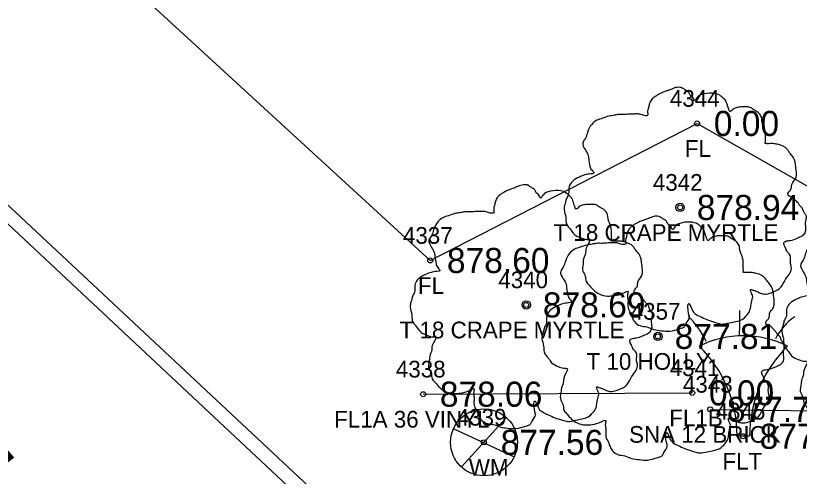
# Model space of a CAD drawing. Extents: x 1622501 to 1626664, y 1117816 to 1121579.
# Drawn here: x 1625412.78 to 1625459.66, y 1120695.23 to 1120722.81 of the extents above; entities that cross this region are included whole.
import ezdxf

# ---------------------------------------------------------------- set-up
doc = ezdxf.new("R2010")
doc.units = 0
for name, color, linetype in [('RD_EX_BldgApp', 7, 'Continuous'), ('RD_EX_BldgApp_txCode', 7, 'Continuous'), ('RD_EX_Conc', 7, 'Continuous'), ('RD_EX_Fence_Other', 7, 'Continuous'), ('RD_EX_Fence_Other_txCode', 7, 'Continuous'), ('RD_EX_Road', 7, 'Continuous'), ('RD_EX_TX_BldgApp_ELEV', 7, 'Continuous'), ('RD_EX_TX_Fence_Other_ELEV', 7, 'Continuous'), ('RD_EX_TX_UT_ELEV', 7, 'Continuous'), ('RD_EX_TX_VEG_ELEV', 7, 'Continuous'), ('RD_EX_UT', 7, 'Continuous'), ('RD_EX_UT_txCode', 7, 'Continuous'), ('RD_EX_VEG', 7, 'Continuous'), ('RD_EX_VEG_txCode', 7, 'Continuous'), ('RD_HC_Data', 7, 'Continuous'), ('RD_SMD_Locator', 7, 'Continuous')]:
    doc.layers.add(name, color=color, linetype=linetype)

msp = doc.modelspace()

# ---------------------------------------------------------------- linework, layer by layer
at = {"layer": 'RD_EX_BldgApp'}
for p, q in [((1625454.325, 1120699.245), (1625464.474, 1120699.109)), ((1625455.937, 1120697.651), (1625456.687, 1120697.651))]:
    msp.add_line(p, q, dxfattribs=at)
for centre, radius, start, end in [((1625449.619, 1120701.293), 4.895, 24.3279, 46.2665), ((1625418.23, 1120704.989), 37.876, 358.0671, 0.2715), ((1625461.2, 1120702.044), 3.283, 123.2906, 154.4886), ((1625456.312, 1120697.651), 5.997, 63.7794, 116.2206), ((1625448.437, 1120697.651), 7.5, 0, 45.8366), ((1625464.187, 1120697.651), 7.5, 134.1634, 180)]:
    msp.add_arc(centre, radius, start, end, dxfattribs=at)
at = {"layer": 'RD_EX_Conc'}
msp.add_lwpolyline([(1625371.324, 1120758.09), (1625374.405, 1120748.878), (1625381, 1120740.913), (1625403.527, 1120719.673), (1625432.461, 1120692.614), (1625438.681, 1120687.207)], dxfattribs=at)
at = {"layer": 'RD_EX_Fence_Other'}
msp.add_line((1625437.153, 1120700.153), (1625453.252, 1120700.233), dxfattribs=at)
msp.add_lwpolyline([(1625435.579, 1120742.173), (1625418.734, 1120725.47), (1625437.576, 1120708.158), (1625453.545, 1120716.361), (1625468.822, 1120707.682)], dxfattribs=at)
at = {"layer": 'RD_EX_Road'}
msp.add_lwpolyline([(1625370.364, 1120757.883), (1625373.672, 1120748.564), (1625380.435, 1120740.201), (1625402.846, 1120719.199), (1625431.886, 1120691.989), (1625438.078, 1120686.6), (1625445.87, 1120680.321), (1625455.5, 1120677.046), (1625462.434, 1120676.301), (1625468.216, 1120676.722), (1625470.162, 1120677.112), (1625477.587, 1120679.763), (1625479.605, 1120680.725), (1625482.392, 1120682.638), (1625486.867, 1120686.354)], dxfattribs=at)
at = {"layer": 'RD_EX_UT'}
for p, q in [((1625439.44, 1120695.812), (1625442.108, 1120698.709)), ((1625438.959, 1120698.108), (1625442.59, 1120696.395))]:
    msp.add_line(p, q, dxfattribs=at)
msp.add_circle((1625440.792, 1120697.27), 2, dxfattribs=at)
at = {"layer": 'RD_EX_VEG'}
for centre, radius in [((1625452.527, 1120711.331), 0.25), ((1625452.514, 1120711.312), 0.0001), ((1625443.319, 1120705.497), 0.25), ((1625443.306, 1120705.478), 0.0001), ((1625451.203, 1120703.613), 0.25), ((1625451.19, 1120703.594), 0.0001)]:
    msp.add_circle(centre, radius, dxfattribs=at)
for points in [[(1625452.659, 1120718.498), (1625452.359, 1120718.523), (1625452.034, 1120718.423), (1625451.784, 1120718.323), (1625451.559, 1120718.248), (1625451.334, 1120718.148), (1625451.035, 1120717.974), (1625450.81, 1120717.774), (1625450.685, 1120717.524), (1625450.635, 1120717.299), (1625450.585, 1120717.024), (1625450.585, 1120716.849), (1625450.46, 1120716.824), (1625450.31, 1120716.849), (1625450.06, 1120716.924), (1625449.81, 1120716.924), (1625449.56, 1120716.924), (1625449.21, 1120716.899), (1625448.86, 1120716.899), (1625448.586, 1120716.849), (1625448.261, 1120716.799), (1625447.886, 1120716.674), (1625447.536, 1120716.549), (1625447.236, 1120716.299), (1625446.986, 1120715.824), (1625446.861, 1120715.475), (1625446.711, 1120715.225), (1625446.861, 1120714.775), (1625447.036, 1120714.425), (1625447.061, 1120714.225), (1625447.136, 1120713.8), (1625447.236, 1120713.575), (1625447.361, 1120713.375), (1625447.286, 1120713.351), (1625446.911, 1120713.301), (1625446.611, 1120713.201), (1625446.187, 1120712.976), (1625445.962, 1120712.751), (1625445.862, 1120712.426), (1625445.837, 1120712.076), (1625445.737, 1120711.876), (1625445.662, 1120711.601), (1625445.637, 1120711.526), (1625445.587, 1120711.201), (1625445.687, 1120710.752), (1625445.712, 1120710.402), (1625445.837, 1120710.177), (1625445.987, 1120710.002), (1625446.162, 1120709.752), (1625446.561, 1120709.527), (1625446.886, 1120709.427), (1625447.086, 1120709.402), (1625446.911, 1120708.902), (1625446.861, 1120708.553), (1625446.736, 1120708.153), (1625446.736, 1120708.078), (1625446.686, 1120707.603), (1625446.836, 1120707.278), (1625446.911, 1120706.903), (1625447.086, 1120706.678), (1625447.361, 1120706.379), (1625447.686, 1120706.154), (1625448.186, 1120706.029), (1625448.586, 1120706.054), (1625449.16, 1120706.229), (1625449.41, 1120706.304), (1625449.385, 1120706.129), (1625449.41, 1120705.754), (1625449.41, 1120705.329), (1625449.56, 1120705.004), (1625449.66, 1120704.729), (1625449.81, 1120704.479), (1625450.135, 1120704.255), (1625450.535, 1120704.18), (1625450.96, 1120704.03), (1625451.409, 1120703.955), (1625451.909, 1120703.93), (1625452.509, 1120704.08), (1625452.784, 1120704.205), (1625452.884, 1120704.379), (1625453.084, 1120704.754), (1625453.034, 1120704.979), (1625453.059, 1120705.579), (1625453.159, 1120705.404), (1625453.334, 1120705.054), (1625453.833, 1120704.754), (1625454.233, 1120704.579), (1625454.708, 1120704.429), (1625455.008, 1120704.354), (1625455.483, 1120704.429), (1625455.857, 1120704.504), (1625456.232, 1120704.629), (1625456.532, 1120704.904), (1625456.707, 1120705.179), (1625456.757, 1120705.454), (1625456.832, 1120705.829), (1625456.882, 1120706.004)], [(1625456.882, 1120706.004), (1625456.807, 1120706.179), (1625456.757, 1120706.429), (1625456.832, 1120706.404), (1625457.007, 1120706.354), (1625457.282, 1120706.229), (1625457.507, 1120706.154), (1625457.832, 1120706.179), (1625458.106, 1120706.279), (1625458.556, 1120706.554), (1625458.831, 1120707.028), (1625459.106, 1120707.428), (1625459.181, 1120707.753), (1625459.131, 1120707.978), (1625459.106, 1120708.478), (1625458.906, 1120708.728), (1625458.856, 1120708.852), (1625458.756, 1120709.252), (1625458.831, 1120709.302), (1625459.106, 1120709.352), (1625459.481, 1120709.477), (1625459.756, 1120709.602), (1625459.981, 1120709.777), (1625460.056, 1120710.002), (1625460.031, 1120710.402), (1625460.081, 1120710.802), (1625460.006, 1120710.952), (1625459.906, 1120711.101), (1625459.831, 1120711.301), (1625459.681, 1120711.451), (1625459.581, 1120711.601), (1625459.481, 1120711.701), (1625459.356, 1120711.851), (1625459.181, 1120711.976), (1625459.031, 1120712.026), (1625458.981, 1120712.176), (1625459.131, 1120712.376), (1625459.181, 1120712.476), (1625459.206, 1120712.701), (1625459.431, 1120713.051), (1625459.481, 1120713.45), (1625459.431, 1120713.875), (1625459.381, 1120714.15), (1625459.231, 1120714.425), (1625459.031, 1120714.675), (1625458.906, 1120714.85), (1625458.731, 1120714.975), (1625458.406, 1120715.1), (1625458.156, 1120715.15), (1625457.807, 1120715.15), (1625457.607, 1120715.2), (1625457.632, 1120715.25), (1625457.632, 1120715.4), (1625457.632, 1120715.675), (1625457.557, 1120716.124), (1625457.407, 1120716.624), (1625457.407, 1120716.649), (1625457.307, 1120716.899), (1625457.082, 1120717.099), (1625456.907, 1120717.199), (1625456.707, 1120717.324), (1625456.457, 1120717.349), (1625456.157, 1120717.349), (1625455.882, 1120717.299), (1625455.682, 1120717.199), (1625455.508, 1120717.074), (1625455.433, 1120717.224), (1625455.333, 1120717.524), (1625455.283, 1120717.674), (1625455.133, 1120717.849), (1625454.908, 1120718.048), (1625454.458, 1120718.173), (1625453.833, 1120718.098), (1625453.533, 1120717.899), (1625453.383, 1120717.724), (1625453.334, 1120717.849), (1625453.134, 1120718.048), (1625453.034, 1120718.223), (1625452.859, 1120718.348), (1625452.709, 1120718.448), (1625452.609, 1120718.498)], [(1625443.451, 1120712.664), (1625443.151, 1120712.689), (1625442.826, 1120712.589), (1625442.576, 1120712.489), (1625442.351, 1120712.414), (1625442.126, 1120712.314), (1625441.826, 1120712.139), (1625441.602, 1120711.939), (1625441.477, 1120711.689), (1625441.427, 1120711.464), (1625441.377, 1120711.19), (1625441.377, 1120711.015), (1625441.252, 1120710.99), (1625441.102, 1120711.015), (1625440.852, 1120711.09), (1625440.602, 1120711.09), (1625440.352, 1120711.09), (1625440.002, 1120711.065), (1625439.652, 1120711.065), (1625439.378, 1120711.015), (1625439.053, 1120710.965), (1625438.678, 1120710.84), (1625438.328, 1120710.715), (1625438.028, 1120710.465), (1625437.778, 1120709.99), (1625437.653, 1120709.64), (1625437.503, 1120709.39), (1625437.653, 1120708.941), (1625437.828, 1120708.591), (1625437.853, 1120708.391), (1625437.928, 1120707.966), (1625438.028, 1120707.741), (1625438.153, 1120707.541), (1625438.078, 1120707.516), (1625437.703, 1120707.466), (1625437.403, 1120707.366), (1625436.979, 1120707.141), (1625436.754, 1120706.916), (1625436.654, 1120706.591), (1625436.629, 1120706.242), (1625436.529, 1120706.042), (1625436.454, 1120705.767), (1625436.429, 1120705.692), (1625436.379, 1120705.367), (1625436.479, 1120704.917), (1625436.504, 1120704.567), (1625436.629, 1120704.342), (1625436.779, 1120704.168), (1625436.954, 1120703.918), (1625437.353, 1120703.693), (1625437.678, 1120703.593), (1625437.878, 1120703.568), (1625437.703, 1120703.068), (1625437.653, 1120702.718), (1625437.528, 1120702.318), (1625437.528, 1120702.243), (1625437.478, 1120701.769), (1625437.628, 1120701.444), (1625437.703, 1120701.069), (1625437.878, 1120700.844), (1625438.153, 1120700.544), (1625438.478, 1120700.319), (1625438.978, 1120700.194), (1625439.378, 1120700.219), (1625439.952, 1120700.394), (1625440.202, 1120700.469), (1625440.177, 1120700.294), (1625440.202, 1120699.919), (1625440.202, 1120699.495), (1625440.352, 1120699.17), (1625440.452, 1120698.895), (1625440.602, 1120698.645), (1625440.927, 1120698.42), (1625441.327, 1120698.345), (1625441.751, 1120698.195), (1625442.201, 1120698.12), (1625442.701, 1120698.095), (1625443.301, 1120698.245), (1625443.576, 1120698.37), (1625443.676, 1120698.545), (1625443.876, 1120698.92), (1625443.826, 1120699.145), (1625443.851, 1120699.745), (1625443.95, 1120699.57), (1625444.125, 1120699.22), (1625444.625, 1120698.92), (1625445.025, 1120698.745), (1625445.5, 1120698.595), (1625445.8, 1120698.52), (1625446.274, 1120698.595), (1625446.649, 1120698.67), (1625447.024, 1120698.795), (1625447.324, 1120699.07), (1625447.499, 1120699.345), (1625447.549, 1120699.62), (1625447.624, 1120699.994), (1625447.674, 1120700.169)], [(1625447.674, 1120700.169), (1625447.599, 1120700.344), (1625447.549, 1120700.594), (1625447.624, 1120700.569), (1625447.799, 1120700.519), (1625448.074, 1120700.394), (1625448.299, 1120700.319), (1625448.623, 1120700.344), (1625448.898, 1120700.444), (1625449.348, 1120700.719), (1625449.623, 1120701.194), (1625449.898, 1120701.594), (1625449.973, 1120701.919), (1625449.923, 1120702.143), (1625449.898, 1120702.643), (1625449.698, 1120702.893), (1625449.648, 1120703.018), (1625449.548, 1120703.418), (1625449.623, 1120703.468), (1625449.898, 1120703.518), (1625450.273, 1120703.643), (1625450.548, 1120703.768), (1625450.773, 1120703.943), (1625450.847, 1120704.168), (1625450.823, 1120704.567), (1625450.872, 1120704.967), (1625450.798, 1120705.117), (1625450.698, 1120705.267), (1625450.623, 1120705.467), (1625450.473, 1120705.617), (1625450.373, 1120705.767), (1625450.273, 1120705.867), (1625450.148, 1120706.017), (1625449.973, 1120706.142), (1625449.823, 1120706.192), (1625449.773, 1120706.342), (1625449.923, 1120706.542), (1625449.973, 1120706.641), (1625449.998, 1120706.866), (1625450.223, 1120707.216), (1625450.273, 1120707.616), (1625450.223, 1120708.041), (1625450.173, 1120708.316), (1625450.023, 1120708.591), (1625449.823, 1120708.841), (1625449.698, 1120709.015), (1625449.523, 1120709.14), (1625449.198, 1120709.265), (1625448.948, 1120709.315), (1625448.598, 1120709.315), (1625448.399, 1120709.365), (1625448.424, 1120709.415), (1625448.424, 1120709.565), (1625448.424, 1120709.84), (1625448.349, 1120710.29), (1625448.199, 1120710.79), (1625448.199, 1120710.815), (1625448.099, 1120711.065), (1625447.874, 1120711.264), (1625447.699, 1120711.364), (1625447.499, 1120711.489), (1625447.249, 1120711.514), (1625446.949, 1120711.514), (1625446.674, 1120711.464), (1625446.474, 1120711.364), (1625446.299, 1120711.239), (1625446.224, 1120711.389), (1625446.125, 1120711.689), (1625446.075, 1120711.839), (1625445.925, 1120712.014), (1625445.7, 1120712.214), (1625445.25, 1120712.339), (1625444.625, 1120712.264), (1625444.325, 1120712.064), (1625444.175, 1120711.889), (1625444.125, 1120712.014), (1625443.925, 1120712.214), (1625443.826, 1120712.389), (1625443.651, 1120712.514), (1625443.501, 1120712.614), (1625443.401, 1120712.664)], [(1625465.687, 1120711.204), (1625465.387, 1120711.229), (1625465.063, 1120711.129), (1625464.813, 1120711.03), (1625464.588, 1120710.955), (1625464.363, 1120710.855), (1625464.063, 1120710.68), (1625463.838, 1120710.48), (1625463.713, 1120710.23), (1625463.663, 1120710.005), (1625463.613, 1120709.73), (1625463.613, 1120709.555), (1625463.488, 1120709.53), (1625463.338, 1120709.555), (1625463.088, 1120709.63), (1625462.839, 1120709.63), (1625462.589, 1120709.63), (1625462.239, 1120709.605), (1625461.889, 1120709.605), (1625461.614, 1120709.555), (1625461.289, 1120709.505), (1625460.914, 1120709.38), (1625460.565, 1120709.255), (1625460.265, 1120709.005), (1625460.015, 1120708.531), (1625459.89, 1120708.181), (1625459.74, 1120707.931), (1625459.89, 1120707.481), (1625460.065, 1120707.131), (1625460.09, 1120706.931), (1625460.165, 1120706.507), (1625460.265, 1120706.282), (1625460.39, 1120706.082), (1625460.315, 1120706.057), (1625459.94, 1120706.007), (1625459.64, 1120705.907), (1625459.215, 1120705.682), (1625458.99, 1120705.457), (1625458.89, 1120705.132), (1625458.865, 1120704.782), (1625458.765, 1120704.582), (1625458.69, 1120704.307), (1625458.665, 1120704.232), (1625458.615, 1120703.908), (1625458.715, 1120703.458), (1625458.74, 1120703.108), (1625458.865, 1120702.883), (1625459.015, 1120702.708), (1625459.19, 1120702.458), (1625459.59, 1120702.233), (1625459.915, 1120702.133), (1625460.115, 1120702.108), (1625459.94, 1120701.609), (1625459.89, 1120701.259), (1625459.765, 1120700.859), (1625459.765, 1120700.784), (1625459.715, 1120700.309), (1625459.865, 1120699.984), (1625459.94, 1120699.61), (1625460.115, 1120699.385), (1625460.39, 1120699.085), (1625460.714, 1120698.86), (1625461.214, 1120698.735), (1625461.614, 1120698.76), (1625462.189, 1120698.935), (1625462.439, 1120699.01), (1625462.414, 1120698.835), (1625462.439, 1120698.46), (1625462.439, 1120698.035), (1625462.589, 1120697.71), (1625462.689, 1120697.435), (1625462.839, 1120697.186), (1625463.163, 1120696.961), (1625463.563, 1120696.886), (1625463.988, 1120696.736), (1625464.438, 1120696.661), (1625464.938, 1120696.636), (1625465.537, 1120696.786), (1625465.812, 1120696.911), (1625465.912, 1120697.086), (1625466.112, 1120697.46), (1625466.062, 1120697.685), (1625466.087, 1120698.285), (1625466.187, 1120698.11), (1625466.362, 1120697.76), (1625466.862, 1120697.46), (1625467.262, 1120697.286), (1625467.736, 1120697.136), (1625468.036, 1120697.061), (1625468.511, 1120697.136), (1625468.886, 1120697.211), (1625469.261, 1120697.336), (1625469.561, 1120697.61), (1625469.736, 1120697.885), (1625469.786, 1120698.16), (1625469.86, 1120698.535), (1625469.91, 1120698.71)], [(1625451.335, 1120710.78), (1625451.035, 1120710.805), (1625450.71, 1120710.705), (1625450.46, 1120710.605), (1625450.235, 1120710.53), (1625450.01, 1120710.43), (1625449.71, 1120710.255), (1625449.486, 1120710.056), (1625449.361, 1120709.806), (1625449.311, 1120709.581), (1625449.261, 1120709.306), (1625449.261, 1120709.131), (1625449.136, 1120709.106), (1625448.986, 1120709.131), (1625448.736, 1120709.206), (1625448.486, 1120709.206), (1625448.236, 1120709.206), (1625447.886, 1120709.181), (1625447.536, 1120709.181), (1625447.262, 1120709.131), (1625446.937, 1120709.081), (1625446.562, 1120708.956), (1625446.212, 1120708.831), (1625445.912, 1120708.581), (1625445.662, 1120708.106), (1625445.537, 1120707.757), (1625445.387, 1120707.507), (1625445.537, 1120707.057), (1625445.712, 1120706.707), (1625445.737, 1120706.507), (1625445.812, 1120706.082), (1625445.912, 1120705.857), (1625446.037, 1120705.657), (1625445.962, 1120705.633), (1625445.587, 1120705.583), (1625445.287, 1120705.483), (1625444.863, 1120705.258), (1625444.638, 1120705.033), (1625444.538, 1120704.708), (1625444.513, 1120704.358), (1625444.413, 1120704.158), (1625444.338, 1120703.883), (1625444.313, 1120703.808), (1625444.263, 1120703.483), (1625444.363, 1120703.034), (1625444.388, 1120702.684), (1625444.513, 1120702.459), (1625444.663, 1120702.284), (1625444.838, 1120702.034), (1625445.237, 1120701.809), (1625445.562, 1120701.709), (1625445.762, 1120701.684), (1625445.587, 1120701.184), (1625445.537, 1120700.835), (1625445.412, 1120700.435), (1625445.412, 1120700.36), (1625445.362, 1120699.885), (1625445.512, 1120699.56), (1625445.587, 1120699.185), (1625445.762, 1120698.96), (1625446.037, 1120698.66), (1625446.362, 1120698.436), (1625446.862, 1120698.311), (1625447.262, 1120698.336), (1625447.836, 1120698.511), (1625448.086, 1120698.586), (1625448.061, 1120698.411), (1625448.086, 1120698.036), (1625448.086, 1120697.611), (1625448.236, 1120697.286), (1625448.336, 1120697.011), (1625448.486, 1120696.761), (1625448.811, 1120696.536), (1625449.211, 1120696.461), (1625449.635, 1120696.312), (1625450.085, 1120696.237), (1625450.585, 1120696.212), (1625451.185, 1120696.361), (1625451.46, 1120696.486), (1625451.56, 1120696.661), (1625451.76, 1120697.036), (1625451.71, 1120697.261), (1625451.735, 1120697.861), (1625451.834, 1120697.686), (1625452.009, 1120697.336), (1625452.509, 1120697.036), (1625452.909, 1120696.861), (1625453.384, 1120696.711), (1625453.684, 1120696.636), (1625454.158, 1120696.711), (1625454.533, 1120696.786), (1625454.908, 1120696.911), (1625455.208, 1120697.186), (1625455.383, 1120697.461), (1625455.433, 1120697.736), (1625455.508, 1120698.111), (1625455.558, 1120698.286)], [(1625455.558, 1120698.286), (1625455.483, 1120698.461), (1625455.433, 1120698.711), (1625455.508, 1120698.685), (1625455.683, 1120698.636), (1625455.958, 1120698.511), (1625456.183, 1120698.436), (1625456.507, 1120698.461), (1625456.782, 1120698.561), (1625457.232, 1120698.836), (1625457.507, 1120699.31), (1625457.782, 1120699.71), (1625457.857, 1120700.035), (1625457.807, 1120700.26), (1625457.782, 1120700.76), (1625457.582, 1120701.009), (1625457.532, 1120701.134), (1625457.432, 1120701.534), (1625457.507, 1120701.584), (1625457.782, 1120701.634), (1625458.157, 1120701.759), (1625458.432, 1120701.884), (1625458.657, 1120702.059), (1625458.731, 1120702.284), (1625458.707, 1120702.684), (1625458.756, 1120703.084), (1625458.682, 1120703.234), (1625458.582, 1120703.383), (1625458.507, 1120703.583), (1625458.357, 1120703.733), (1625458.257, 1120703.883), (1625458.157, 1120703.983), (1625458.032, 1120704.133), (1625457.857, 1120704.258), (1625457.707, 1120704.308), (1625457.657, 1120704.458), (1625457.807, 1120704.658), (1625457.857, 1120704.758), (1625457.882, 1120704.983), (1625458.107, 1120705.333), (1625458.157, 1120705.732), (1625458.107, 1120706.157), (1625458.057, 1120706.432), (1625457.907, 1120706.707), (1625457.707, 1120706.957), (1625457.582, 1120707.132), (1625457.407, 1120707.257), (1625457.082, 1120707.382), (1625456.832, 1120707.432), (1625456.482, 1120707.432), (1625456.283, 1120707.482), (1625456.308, 1120707.532), (1625456.308, 1120707.682), (1625456.308, 1120707.957), (1625456.233, 1120708.406), (1625456.083, 1120708.906), (1625456.083, 1120708.931), (1625455.983, 1120709.181), (1625455.758, 1120709.381), (1625455.583, 1120709.481), (1625455.383, 1120709.606), (1625455.133, 1120709.631), (1625454.833, 1120709.631), (1625454.558, 1120709.581), (1625454.358, 1120709.481), (1625454.183, 1120709.356), (1625454.108, 1120709.506), (1625454.009, 1120709.806), (1625453.959, 1120709.956), (1625453.809, 1120710.13), (1625453.584, 1120710.33), (1625453.134, 1120710.455), (1625452.509, 1120710.38), (1625452.209, 1120710.181), (1625452.059, 1120710.006), (1625452.009, 1120710.13), (1625451.809, 1120710.33), (1625451.71, 1120710.505), (1625451.535, 1120710.63), (1625451.385, 1120710.73), (1625451.285, 1120710.78)]]:
    msp.add_spline(points, degree=3, dxfattribs=at)
at = {"layer": 'RD_SMD_Locator'}
for centre in [(1625453.545, 1120716.361), (1625452.527, 1120711.331), (1625437.576, 1120708.158), (1625443.319, 1120705.497), (1625451.203, 1120703.613), (1625437.153, 1120700.153), (1625453.252, 1120700.233), (1625454.325, 1120699.245), (1625456.284, 1120697.633), (1625440.792, 1120697.27)]:
    msp.add_circle(centre, 0.15, dxfattribs=at)

# ---------------------------------------------------------------- texts
at = {"layer": 'RD_EX_BldgApp_txCode'}
for s, p in [('4343', (1625452.695, 1120700.245)), ('4345', (1625454.654, 1120698.633)), ('SNA 12 BRICK', (1625449.475, 1120697.245)), ('FLT', (1625455.064, 1120695.633))]:
    msp.add_text(s, height=1, dxfattribs=at).set_placement(p)
at = {"layer": 'RD_EX_Fence_Other_txCode'}
for s, p in [('4344', (1625451.915, 1120717.361)), ('FL', (1625452.812, 1120714.361)), ('4337', (1625435.946, 1120709.158)), ('FL', (1625436.843, 1120706.158)), ('4338', (1625435.523, 1120701.153)), ('4341', (1625451.906, 1120701.233)), ('FL1B', (1625451.882, 1120698.233)), ('FL1A 36 VINYL', (1625431.83, 1120698.153))]:
    msp.add_text(s, height=1, dxfattribs=at).set_placement(p)
at = {"layer": 'RD_EX_TX_BldgApp_ELEV'}
for s, p in [('877.77', (1625455.325, 1120698.495)), ('877.64', (1625457.284, 1120696.883))]:
    msp.add_text(s, height=1.5, dxfattribs=at).set_placement(p)
at = {"layer": 'RD_EX_TX_Fence_Other_ELEV'}
for s, p in [('0.00', (1625454.545, 1120715.611)), ('878.60', (1625438.576, 1120707.408)), ('878.06', (1625438.153, 1120699.403)), ('0.00', (1625454.252, 1120699.483))]:
    msp.add_text(s, height=1.5, dxfattribs=at).set_placement(p)
at = {"layer": 'RD_EX_TX_UT_ELEV'}
msp.add_text('877.56', height=1.5, dxfattribs=at).set_placement((1625441.792, 1120696.52))
at = {"layer": 'RD_EX_TX_VEG_ELEV'}
for s, p in [('878.94', (1625453.527, 1120710.581)), ('878.69', (1625444.319, 1120704.747)), ('877.81', (1625452.203, 1120702.863))]:
    msp.add_text(s, height=1.5, dxfattribs=at).set_placement(p)
at = {"layer": 'RD_EX_UT_txCode'}
for s, p in [('4339', (1625439.162, 1120698.27)), ('WM', (1625439.887, 1120695.27))]:
    msp.add_text(s, height=1, dxfattribs=at).set_placement(p)
at = {"layer": 'RD_EX_VEG_txCode'}
for s, p in [('4342', (1625450.897, 1120712.331)), ('T 18 CRAPE MYRTLE', (1625444.956, 1120709.331)), ('4340', (1625441.65, 1120706.497)), ('4357', (1625449.573, 1120704.613)), ('T 18 CRAPE MYRTLE', (1625435.748, 1120703.497)), ('T 10 HOLLY', (1625446.935, 1120701.613))]:
    msp.add_text(s, height=1, dxfattribs=at).set_placement(p)
at = {"layer": 'RD_HC_Data'}
msp.add_text('N 40%%d 21\' 52" W', height=6, rotation=310.3644, dxfattribs=at).set_placement((1625387.11, 1120717.187))

doc.saveas('drawing.dxf')
